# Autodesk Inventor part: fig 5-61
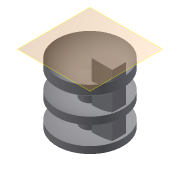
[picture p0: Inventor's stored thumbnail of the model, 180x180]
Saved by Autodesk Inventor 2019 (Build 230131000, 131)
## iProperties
Created: 2004-05
Part Number: fig 5-61
Document SubType Name: Modeling
Designer: CADCIM Technologies
Manufacturer: Standard
Standards Organization: Custom
Density: 1 g/cm^3
Material: Generic
Appearance: Default
Author: CADCIM Technologies
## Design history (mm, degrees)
sketch "Sketch1"
  geometry: L1 (0.098, 22.743)-(0.098, 0.516); L2 (-3.621, 19.305)-(-3.621, 13.061); L3 (-3.621, 10.379)-(-3.621, 3.25); L4 (-3.664, 0.516)-(0.098, 0.516); L5 (-13.694, 4.7)-(-13.694, 1.836); L6 (-13.694, 26.851)-(-13.694, 23.014); L7 (-13.694, 15.335)-(-13.694, 12.343); A1 r 10.546 centre (-4.597, 32.185) between (-13.694, 26.851) and (0.098, 22.743); A2 r 21.828 centre (-4.597, 32.185) between (-13.694, 12.343) and (-3.621, 10.379); A3 r 12.918 centre (-4.597, 32.185) between (-13.694, 23.014) and (-3.621, 19.305); A4 r 19.149 centre (-4.597, 32.185) between (-13.694, 15.335) and (-3.621, 13.061); A5 r 28.952 centre (-4.597, 32.185) between (-13.694, 4.7) and (-3.621, 3.25); A6 r 31.683 centre (-4.597, 32.185) between (-13.694, 1.836) and (-3.664, 0.516)
  constraints: 14 end point, 12 point on circle, 6 centre point, 4 perpendicular, 2 parallel, 1 vertical
revolve "Revolution1" sketch "Sketch1" stored, may be unused: angle "d0" = 90 deg
workplane "Work Plane1"
sketch "Sketch2"
  geometry: L1 (3.408, -2.846)-(12.06, -2.846); L2 (12.06, -2.846)-(12.06, 2.873); L3 (12.06, 2.873)-(3.408, 2.873); L4 (3.408, 2.873)-(3.408, -2.846)
  constraints: 8 end point, 2 parallel, 1 horizontal, 1 perpendicular
extrude "Extrusion3" join sketch "Sketch2" extent not by distance; stored distance "d8" = 10; taper "d9" = 0 deg
body "Solid1"
